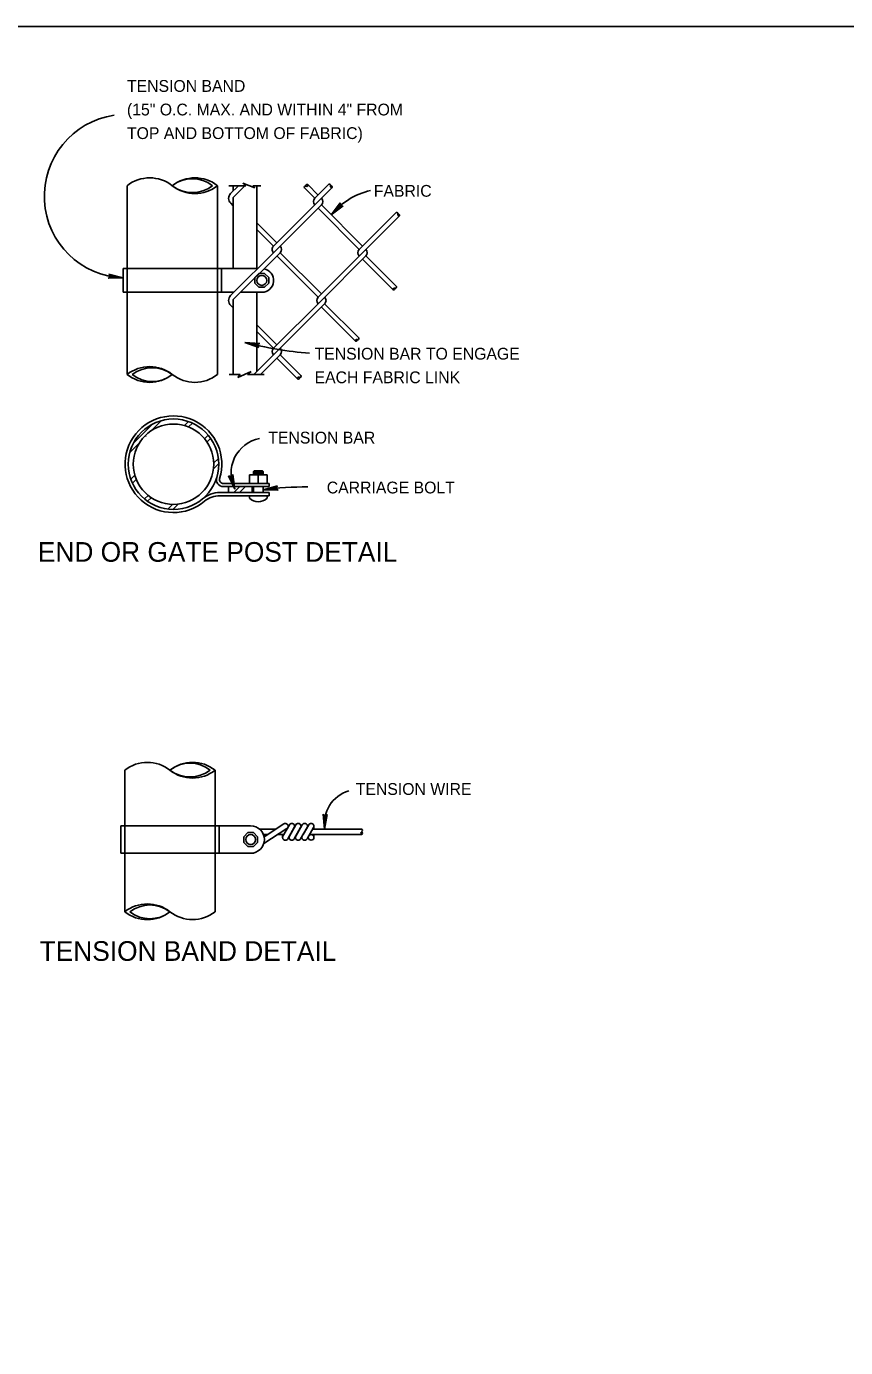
# Model space of a CAD drawing. Extents: x -123486 to -116575, y -107066 to -101122.
# Drawn here: x -118786 to -118370, y -101794 to -101122 of the extents above; entities that cross this region are included whole.
import ezdxf

# ---------------------------------------------------------------- set-up
doc = ezdxf.new("R2010")
doc.units = 0
doc.layers.add('Default', color=7, linetype='Continuous')
doc.layers.add('G-MARK', color=7, linetype='Continuous')

msp = doc.modelspace()

# ---------------------------------------------------------------- linework, layer by layer
at = {"layer": 'Default'}
msp.add_lwpolyline([(-119542.38, -101122.36), (-117742.38, -101122.36), (-117742.38, -102572.36), (-119542.38, -102572.36)], close=True, dxfattribs=at)
at = {"layer": 'G-MARK'}
for p, q in [((-118734.9, -101203.37), (-118734.9, -101245.54)), ((-118688.9, -101203.37), (-118688.9, -101245.54)), ((-118683.09, -101203.37), (-118674.59, -101203.37)), ((-118682.24, -101207.28), (-118678.33, -101203.37)), ((-118680.9, -101209.29), (-118674.98, -101203.37)), ((-118680.9, -101203.37), (-118680.9, -101205.94)), ((-118674.59, -101203.37), (-118676.09, -101202.09)), ((-118676.09, -101202.09), (-118669.87, -101204.5)), ((-118670.94, -101203.37), (-118666.97, -101203.37)), ((-118669.87, -101204.5), (-118670.94, -101203.37)), ((-118668.9, -101203.37), (-118668.9, -101245.54)), ((-118644.76, -101204.5), (-118639.48, -101209.78)), ((-118643.08, -101202.83), (-118637.8, -101208.1)), ((-118639.48, -101209.78), (-118632.35, -101202.65)), ((-118637.8, -101211.45), (-118630.68, -101204.33)), ((-118680.9, -101209.29), (-118680.9, -101245.54)), ((-118682.22, -101212.29), (-118680.9, -101213.61)), ((-118660.43, -101234.08), (-118637.8, -101211.45)), ((-118658.76, -101235.75), (-118636.13, -101213.13)), ((-118637.8, -101214.8), (-118616.85, -101235.76)), ((-118636.13, -101213.13), (-118615.17, -101234.08)), ((-118631.12, -101218.14), (-118626.56, -101212.09)), ((-118631.12, -101218.14), (-118626.63, -101212.59)), ((-118631.12, -101218.14), (-118626.59, -101212.92)), ((-118631.12, -101218.14), (-118626.5, -101213.18)), ((-118631.12, -101218.14), (-118626.34, -101213.4)), ((-118631.12, -101218.14), (-118626.18, -101213.53)), ((-118631.12, -101218.14), (-118625.03, -101213.62)), ((-118631.12, -101218.14), (-118625.92, -101213.65)), ((-118631.12, -101218.14), (-118625.59, -101213.7)), ((-118616.85, -101235.76), (-118598.05, -101216.95)), ((-118668.9, -101222.26), (-118658.76, -101232.41)), ((-118615.17, -101237.43), (-118596.38, -101218.63)), ((-118668.9, -101225.61), (-118660.43, -101234.08)), ((-118682.24, -101259.23), (-118658.76, -101235.76)), ((-118657.08, -101237.43), (-118680.9, -101261.25)), ((-118657.08, -101237.43), (-118636.13, -101258.38)), ((-118637.8, -101260.06), (-118615.18, -101237.43)), ((-118658.76, -101239.1), (-118637.8, -101260.06)), ((-118636.13, -101261.73), (-118613.5, -101239.1)), ((-118615.18, -101240.78), (-118599.67, -101256.29)), ((-118613.5, -101239.1), (-118597.99, -101254.61)), ((-118736.9, -101250.29), (-118744.48, -101250.45)), ((-118736.9, -101250.29), (-118744.22, -101248.3)), ((-118736.9, -101250.29), (-118744.04, -101250.2)), ((-118736.9, -101250.29), (-118743.81, -101248.69)), ((-118736.9, -101250.29), (-118743.8, -101249.96)), ((-118736.9, -101250.29), (-118743.65, -101248.99)), ((-118736.9, -101250.29), (-118743.65, -101249.73)), ((-118736.9, -101250.29), (-118743.58, -101249.26)), ((-118736.9, -101250.29), (-118743.58, -101249.47)), ((-118736.9, -101245.54), (-118668.55, -101245.54)), ((-118736.9, -101245.54), (-118736.9, -101257.54)), ((-118734.9, -101245.54), (-118734.9, -101257.54)), ((-118688.9, -101245.54), (-118688.9, -101257.54)), ((-118686.9, -101245.54), (-118686.9, -101257.54)), ((-118669.9, -101250.1), (-118667.85, -101248.04)), ((-118669.9, -101252.99), (-118669.9, -101250.1)), ((-118667.85, -101248.04), (-118664.95, -101248.04)), ((-118664.95, -101248.04), (-118662.9, -101250.09)), ((-118662.9, -101252.99), (-118662.9, -101250.09)), ((-118736.9, -101257.54), (-118680.55, -101257.54)), ((-118734.9, -101257.54), (-118734.9, -101299.37)), ((-118688.9, -101257.54), (-118688.9, -101299.37)), ((-118680.9, -101257.54), (-118680.9, -101257.89)), ((-118677.2, -101257.54), (-118666.4, -101257.54)), ((-118669.9, -101252.99), (-118667.85, -101255.04)), ((-118668.9, -101257.54), (-118668.9, -101297.84)), ((-118667.85, -101255.04), (-118664.95, -101255.04)), ((-118664.95, -101255.04), (-118662.9, -101252.99)), ((-118680.9, -101265.56), (-118682.22, -101264.24)), ((-118680.9, -101261.25), (-118680.9, -101299.37)), ((-118660.43, -101286.03), (-118636.13, -101261.73)), ((-118657.09, -101286.03), (-118634.45, -101263.41)), ((-118636.13, -101265.08), (-118618.73, -101282.48)), ((-118634.45, -101263.41), (-118617.06, -101280.8)), ((-118658.76, -101284.36), (-118668.9, -101274.21)), ((-118660.43, -101286.03), (-118668.9, -101277.56)), ((-118675.01, -101283.04), (-118667.92, -101285.72)), ((-118675.01, -101283.04), (-118667.45, -101283.6)), ((-118675.01, -101283.04), (-118668.28, -101285.29)), ((-118675.01, -101283.04), (-118668.42, -101284.98)), ((-118675.01, -101283.04), (-118668.47, -101284.71)), ((-118675.01, -101283.04), (-118668.35, -101284.25)), ((-118675.01, -101283.04), (-118668.17, -101284.03)), ((-118675.01, -101283.04), (-118667.91, -101283.81)), ((-118675.01, -101283.04), (-118668.45, -101284.5)), ((-118670.43, -101299.37), (-118657.09, -101286.03)), ((-118667.08, -101299.37), (-118657.09, -101289.38)), ((-118658.76, -101291.05), (-118648.17, -101301.64)), ((-118657.09, -101289.38), (-118646.5, -101299.97)), ((-118671.8, -101297.86), (-118678.55, -101300.97)), ((-118673.6, -101299.37), (-118671.8, -101297.86)), ((-118682.91, -101299.37), (-118677.35, -101299.37)), ((-118678.55, -101300.97), (-118677.35, -101299.37)), ((-118673.6, -101299.37), (-118665.26, -101299.37)), ((-118731.7, -101334.38), (-118721.94, -101324.62)), ((-118722.23, -101327.74), (-118717.31, -101322.81)), ((-118705.71, -101325.36), (-118703.67, -101323.32)), ((-118703.61, -101326.08), (-118701.66, -101324.13)), ((-118725.28, -101330.79), (-118725.23, -101330.73)), ((-118695.47, -101332.09), (-118693.65, -101330.27)), ((-118694.27, -101333.72), (-118692.43, -101331.88)), ((-118733.51, -101339.02), (-118728.58, -101334.09)), ((-118691.01, -101347.43), (-118688.31, -101344.73)), ((-118690.88, -101344.46), (-118688.5, -101342.08)), ((-118733, -101352.65), (-118730.97, -101350.61)), ((-118680.13, -101357.73), (-118683.29, -101350.84)), ((-118680.13, -101357.73), (-118682.89, -101351.14)), ((-118680.13, -101357.73), (-118682.57, -101351.27)), ((-118680.13, -101357.73), (-118682.3, -101351.31)), ((-118680.13, -101357.73), (-118682.03, -101351.28)), ((-118680.13, -101357.73), (-118682.01, -101351.35)), ((-118680.13, -101357.73), (-118681.84, -101351.2)), ((-118680.13, -101357.73), (-118681.62, -101351.03)), ((-118680.13, -101357.73), (-118681.41, -101350.75)), ((-118680.13, -101357.73), (-118681.21, -101350.22)), ((-118672.69, -101350.37), (-118672.69, -101354.81)), ((-118672.69, -101350.37), (-118663.69, -101350.37)), ((-118670.69, -101348.74), (-118670.29, -101348.34)), ((-118670.69, -101348.74), (-118670.69, -101350.37)), ((-118670.69, -101348.74), (-118665.69, -101348.74)), ((-118670.69, -101349.14), (-118665.69, -101349.14)), ((-118670.69, -101349.54), (-118665.69, -101349.54)), ((-118670.69, -101349.94), (-118665.69, -101349.94)), ((-118670.29, -101348.34), (-118666.09, -101348.34)), ((-118670.29, -101348.54), (-118666.09, -101348.54)), ((-118670.29, -101348.94), (-118666.09, -101348.94)), ((-118670.29, -101349.34), (-118666.09, -101349.34)), ((-118670.29, -101349.74), (-118666.09, -101349.74)), ((-118670.29, -101350.14), (-118666.09, -101350.14)), ((-118668.19, -101350.37), (-118668.19, -101354.81)), ((-118665.69, -101348.74), (-118666.09, -101348.34)), ((-118665.69, -101348.74), (-118665.69, -101350.37)), ((-118663.69, -101350.37), (-118663.69, -101354.81)), ((-118732.19, -101354.66), (-118730.24, -101352.72)), ((-118685.88, -101354.81), (-118662.73, -101354.81)), ((-118685.88, -101356.41), (-118662.73, -101356.41)), ((-118683.31, -101356.41), (-118683.31, -101359.41)), ((-118680.54, -101359.41), (-118677.54, -101356.41)), ((-118677.71, -101359.41), (-118674.71, -101356.41)), ((-118671.31, -101356.41), (-118671.31, -101359.41)), ((-118670.69, -101356.41), (-118670.69, -101359.41)), ((-118665.69, -101357.99), (-118658.36, -101356.05)), ((-118665.69, -101357.99), (-118658.73, -101356.4)), ((-118665.69, -101356.41), (-118665.69, -101359.41)), ((-118665.69, -101357.99), (-118658.91, -101356.69)), ((-118665.69, -101357.99), (-118659, -101356.95)), ((-118665.69, -101357.99), (-118659.01, -101357.22)), ((-118665.69, -101357.99), (-118658.96, -101357.42)), ((-118665.69, -101357.99), (-118658.83, -101357.67)), ((-118665.69, -101357.99), (-118658.59, -101357.92)), ((-118665.69, -101357.99), (-118658.11, -101358.21)), ((-118662.73, -101354.81), (-118662.73, -101356.41)), ((-118726.05, -101362.67), (-118724.23, -101360.85)), ((-118724.45, -101363.89), (-118722.6, -101362.05)), ((-118714.24, -101367.83), (-118711.86, -101365.45)), ((-118711.6, -101368.01), (-118708.9, -101365.31)), ((-118687.74, -101359.41), (-118662.73, -101359.41)), ((-118687.74, -101361.01), (-118662.73, -101361.01)), ((-118675.31, -101361.01), (-118663.31, -101361.01)), ((-118672.69, -101361.01), (-118672.69, -101362.31)), ((-118663.69, -101361.01), (-118663.69, -101362.31)), ((-118662.73, -101359.41), (-118662.73, -101361.01)), ((-118736.09, -101500.64), (-118736.09, -101528.89)), ((-118690.09, -101500.64), (-118690.09, -101528.89)), ((-118634.58, -101530.56), (-118635.26, -101523.01)), ((-118634.58, -101530.56), (-118634.97, -101523.43)), ((-118634.58, -101530.56), (-118634.72, -101523.66)), ((-118634.58, -101530.56), (-118633.09, -101523.12)), ((-118634.58, -101530.56), (-118633.45, -101523.56)), ((-118634.58, -101530.56), (-118633.74, -101523.74)), ((-118634.58, -101530.56), (-118634.47, -101523.79)), ((-118634.58, -101530.56), (-118634, -101523.83)), ((-118634.58, -101530.56), (-118634.21, -101523.85)), ((-118634.58, -101530.56), (-118634.22, -101523.92)), ((-118738.09, -101528.89), (-118672.09, -101528.89)), ((-118738.09, -101528.89), (-118738.09, -101542.89)), ((-118736.09, -101528.89), (-118736.09, -101542.89)), ((-118690.09, -101528.89), (-118690.09, -101542.89)), ((-118688.09, -101528.89), (-118688.09, -101542.89)), ((-118675.59, -101534.45), (-118673.54, -101532.39)), ((-118673.54, -101532.39), (-118670.64, -101532.39)), ((-118670.64, -101532.39), (-118668.59, -101534.44)), ((-118667.56, -101530.56), (-118659.23, -101530.56)), ((-118665.55, -101533.39), (-118663.62, -101533.39)), ((-118665.39, -101537.91), (-118653.66, -101530.33)), ((-118665.24, -101534.45), (-118655.19, -101527.96)), ((-118658.39, -101533.39), (-118655.24, -101533.39)), ((-118655.84, -101533.39), (-118655.84, -101534.81)), ((-118652.38, -101528.44), (-118655.65, -101534.1)), ((-118655.24, -101533.39), (-118655.24, -101533.39)), ((-118654.01, -101530.56), (-118653.61, -101530.56)), ((-118649.93, -101529.85), (-118653.19, -101535.5)), ((-118649.11, -101528.44), (-118652.38, -101534.1)), ((-118646.65, -101529.85), (-118649.93, -101535.52)), ((-118645.83, -101528.44), (-118649.11, -101534.1)), ((-118643.38, -101529.85), (-118646.65, -101535.52)), ((-118642.56, -101528.44), (-118645.42, -101533.39)), ((-118640.11, -101529.85), (-118643.38, -101535.52)), ((-118642.15, -101533.39), (-118615.63, -101533.39)), ((-118640.52, -101530.56), (-118615.63, -101530.56)), ((-118639.92, -101529.14), (-118639.92, -101530.56)), ((-118639.92, -101530.56), (-118639.92, -101530.56)), ((-118639.92, -101533.39), (-118639.92, -101534.81)), ((-118675.59, -101537.34), (-118675.59, -101534.45)), ((-118675.59, -101537.34), (-118673.54, -101539.39)), ((-118673.54, -101539.39), (-118670.64, -101539.39)), ((-118670.64, -101539.39), (-118668.59, -101537.34)), ((-118668.59, -101537.34), (-118668.59, -101534.44)), ((-118738.09, -101542.89), (-118672.09, -101542.89)), ((-118736.09, -101542.89), (-118736.09, -101572.64)), ((-118690.09, -101542.89), (-118690.09, -101572.64))]:
    msp.add_line(p, q, dxfattribs=at)
for points in [[(-118625.03, -101213.62), (-118625.59, -101213.7), (-118625.92, -101213.65), (-118626.18, -101213.53), (-118626.36, -101213.38), (-118626.5, -101213.18), (-118626.59, -101212.92), (-118626.63, -101212.59), (-118626.56, -101212.09)], [(-118744.22, -101248.3), (-118743.81, -101248.69), (-118743.65, -101248.99), (-118743.58, -101249.26), (-118743.59, -101249.5), (-118743.65, -101249.73), (-118743.8, -101249.96), (-118744.04, -101250.2), (-118744.48, -101250.45)], [(-118667.92, -101285.72), (-118668.28, -101285.29), (-118668.42, -101284.98), (-118668.47, -101284.71), (-118668.43, -101284.47), (-118668.35, -101284.25), (-118668.17, -101284.03), (-118667.91, -101283.81), (-118667.45, -101283.6)], [(-118681.21, -101350.22), (-118681.41, -101350.75), (-118681.62, -101351.03), (-118681.84, -101351.2), (-118682.06, -101351.28), (-118682.3, -101351.31), (-118682.57, -101351.27), (-118682.89, -101351.14), (-118683.29, -101350.84)], [(-118658.11, -101358.21), (-118658.59, -101357.92), (-118658.83, -101357.67), (-118658.96, -101357.42), (-118659.01, -101357.19), (-118659, -101356.95), (-118658.91, -101356.69), (-118658.73, -101356.4), (-118658.36, -101356.05)], [(-118633.09, -101523.12), (-118633.45, -101523.56), (-118633.74, -101523.74), (-118634, -101523.83), (-118634.24, -101523.84), (-118634.47, -101523.79), (-118634.72, -101523.66), (-118634.97, -101523.43), (-118635.26, -101523.01)]]:
    msp.add_lwpolyline(points, dxfattribs=at)
for centre, radius in [((-118666.4, -101251.54), 2.5), ((-118711.31, -101345.01), 23), ((-118711.31, -101345.01), 20.44), ((-118672.09, -101535.89), 2.5)]:
    msp.add_circle(centre, radius, dxfattribs=at)
for centre, radius, start, end in [((-118735.36, -101208.71), 41.61, 98.41789, 267.87913), ((-118723.4, -101217.91), 18.53, 51.64353, 128.35647), ((-118700.4, -101217.91), 18.53, 51.64198, 128.35802), ((-118701.68, -101216.3), 16.48, 51.66691, 128.33309), ((-118700.4, -101188.84), 18.53, 231.64198, 308.35802), ((-118701.68, -101189.97), 16.86, 232.67656, 307.32344), ((-118644.17, -101204.25), 0.638, 66.86495, 203.13505), ((-118643.33, -101203.41), 0.638, 66.86495, 203.13505), ((-118643.67, -101203.08), 0.638, 246.95895, 23.04105), ((-118632.1, -101203.24), 0.638, 336.86495, 113.13505), ((-118630.93, -101203.74), 0.638, 156.95895, 293.04105), ((-118631.26, -101204.08), 0.638, 336.86495, 113.13505), ((-118679.73, -101209.78), 3.54, 135.19909, 225.53136), ((-118637.8, -101211.45), 2.37, 135, 225), ((-118637.8, -101211.45), 2.37, 315, 45), ((-118602.87, -101241.61), 36.73, 103.12354, 140.27369), ((-118597.8, -101217.54), 0.638, 336.86495, 113.13505), ((-118596.63, -101218.04), 0.638, 156.95895, 293.04105), ((-118596.96, -101218.38), 0.638, 336.86495, 113.13505), ((-118658.76, -101235.75), 2.37, 135, 225.06845), ((-118658.76, -101235.75), 2.37, 315, 45), ((-118615.18, -101237.43), 2.36, 135, 225), ((-118615.18, -101237.43), 2.37, 315, 44.93155), ((-118666.4, -101251.54), 6, 270, 79.41716), ((-118599.08, -101256.04), 0.638, 66.95895, 203.04105), ((-118599.42, -101255.7), 0.638, 246.86495, 23.13505), ((-118598.58, -101254.86), 0.638, 246.86495, 23.13505), ((-118679.73, -101261.72), 3.54, 135.19909, 225.53136), ((-118636.13, -101261.73), 2.37, 135, 225), ((-118636.13, -101261.73), 2.37, 315, 45.06845), ((-118628.05, -101103.94), 185.15, 255.30758, 265.62003), ((-118618.14, -101282.23), 0.638, 66.95895, 203.04105), ((-118618.48, -101281.89), 0.638, 246.86495, 23.13505), ((-118617.64, -101281.05), 0.638, 246.86495, 23.13505), ((-118658.76, -101287.7), 2.36, 135, 225), ((-118658.76, -101287.7), 2.37, 315, 45), ((-118723.4, -101313.91), 18.53, 51.64198, 128.35802), ((-118722.12, -101312.78), 16.86, 52.67656, 127.32344), ((-118723.4, -101284.84), 18.53, 231.64198, 308.35802), ((-118722.12, -101286.45), 16.48, 231.66691, 308.33309), ((-118700.4, -101284.84), 18.53, 231.64353, 308.35647), ((-118647.58, -101301.39), 0.638, 66.95895, 203.04105), ((-118647.92, -101301.06), 0.638, 246.86495, 23.13505), ((-118647.08, -101300.22), 0.638, 246.86495, 23.13505), ((-118711.3, -101345.02), 24.59, 342.656, 310.08466), ((-118663.95, -101349.61), 18.1, 101.39184, 206.64661), ((-118685.88, -101352.81), 3.6, 162.94838, 270), ((-118685.88, -101352.81), 2, 162.94838, 270), ((-118644.05, -101518.98), 162.44, 89.62269, 97.65609), ((-118687.74, -101373.01), 13.6, 90, 130.09058), ((-118687.74, -101373.01), 12, 90, 130.09058), ((-118668.19, -101357.47), 6.61, 227.13447, 312.86553), ((-118724.59, -101515.17), 18.53, 51.64353, 128.35647), ((-118701.59, -101515.17), 18.53, 51.64198, 128.35802), ((-118702.87, -101513.56), 16.48, 51.66691, 128.33309), ((-118701.59, -101486.11), 18.53, 231.64198, 308.35802), ((-118702.87, -101487.23), 16.86, 232.67656, 307.32344), ((-118616.75, -101528.19), 17.98, 107.75683, 187.57221), ((-118672.09, -101535.89), 7, 270, 90), ((-118654.43, -101529.14), 1.42, 302.86032, 122.88124), ((-118651.15, -101529.14), 1.42, 329.9793, 149.99681), ((-118647.88, -101529.14), 1.42, 329.9793, 149.99681), ((-118647.88, -101529.14), 1.42, 46.43944, 149.99681), ((-118647.88, -101529.14), 1.42, 329.97424, 150.00186), ((-118647.88, -101529.14), 1.42, 329.9793, 39.93459), ((-118644.61, -101529.14), 1.42, 329.9793, 149.99681), ((-118641.33, -101534.81), 1.42, 0, 180), ((-118641.33, -101529.14), 1.42, 329.9793, 149.99681), ((-118641.33, -101529.14), 1.42, 329.9793, 149.99681), ((-118615.2, -101532.69), 0.827, 121.06956, 238.93044), ((-118616.06, -101531.27), 0.827, 301.06956, 58.93044), ((-118616.06, -101532.69), 0.827, 301.06956, 58.93044), ((-118654.42, -101534.8), 1.42, 150.38094, 330.38259), ((-118651.15, -101534.81), 1.42, 149.9871, 329.98901), ((-118647.88, -101534.81), 1.42, 149.9871, 329.98901), ((-118644.61, -101534.81), 1.42, 149.9871, 329.98901), ((-118641.33, -101534.81), 1.42, 180, 0), ((-118724.59, -101587.17), 18.53, 51.64198, 128.35802), ((-118724.59, -101558.11), 18.53, 231.64198, 308.35802), ((-118723.31, -101586.04), 16.86, 52.67656, 127.32344), ((-118723.31, -101559.71), 16.48, 231.66691, 308.33309), ((-118701.59, -101558.1), 18.53, 231.64353, 308.35647)]:
    msp.add_arc(centre, radius, start, end, dxfattribs=at)

# ---------------------------------------------------------------- texts
for s, height, p in [('TENSION BAND', 6, (-118734.95, -101155.63)), ('(15" O.C. MAX. AND WITHIN 4" FROM', 6, (-118734.95, -101167.63)), ('TOP AND BOTTOM OF FABRIC)', 6, (-118734.95, -101179.63)), ('FABRIC', 6, (-118609.47, -101208.99)), ('TENSION BAR TO ENGAGE ', 6, (-118639.58, -101291.81)), ('EACH FABRIC LINK', 6, (-118639.58, -101303.81)), ('TENSION BAR', 6, (-118663.11, -101334.49)), ('CARRIAGE BOLT', 6, (-118633.38, -101359.87)), ('END OR GATE POST DETAIL', 10, (-118780.27, -101394.62)), ('TENSION WIRE', 6, (-118618.63, -101513.2)), ('TENSION BAND DETAIL', 10, (-118779.34, -101597.59))]:
    msp.add_text(s, height=height, dxfattribs=at).set_placement(p)

doc.saveas('drawing.dxf')
